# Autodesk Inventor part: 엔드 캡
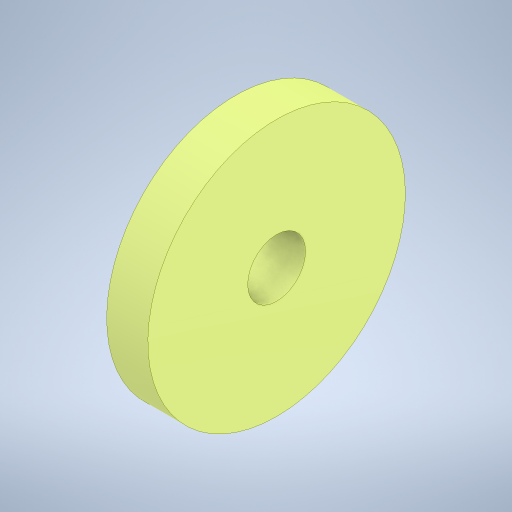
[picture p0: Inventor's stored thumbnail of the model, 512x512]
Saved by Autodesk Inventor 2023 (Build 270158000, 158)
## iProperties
Created: 2026-03
Part Number: 엔드 캡
Material: 강철, 연강
Document SubType Name: Modeling
Designer: home
Density: 7.85 g/cm^3
Appearance: 기본값
Author: jhkim
Sending System: Autodesk Inventor 2026
Preprocessor: ST-DEVELOPER v20.1
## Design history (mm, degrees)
feature "솔리드1"
node "솔리드2"
